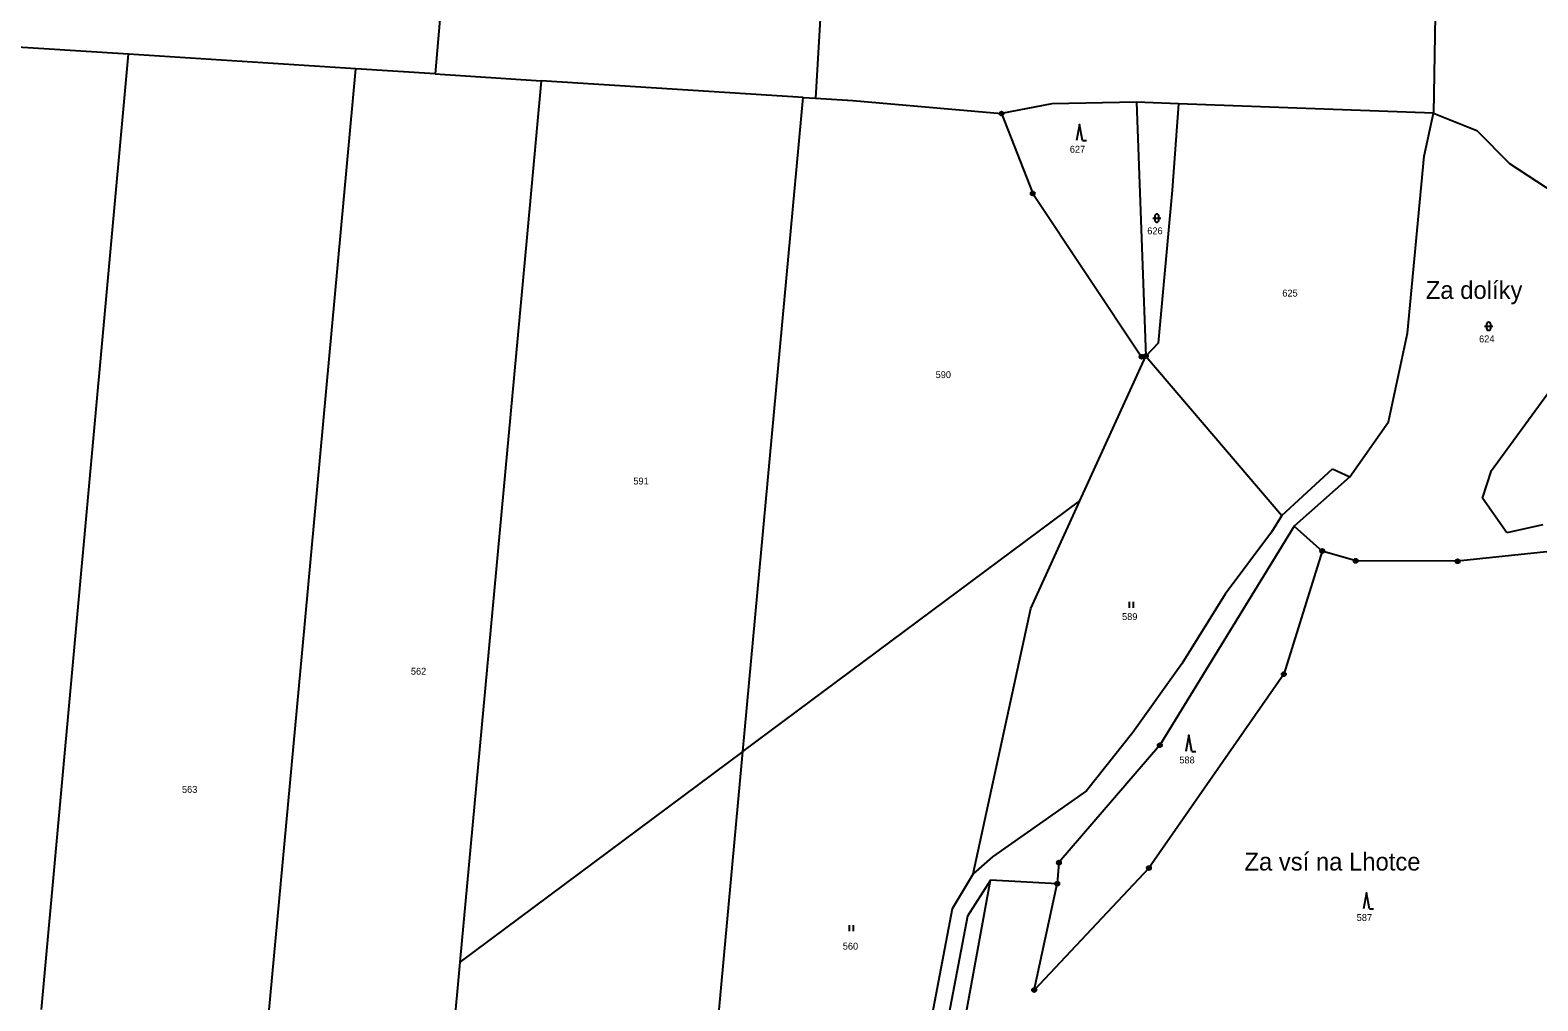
# Model space of a CAD drawing. Extents: x -719614 to -717765, y -1095834 to -1093862.
# Drawn here: x -718922.3 to -718549.9, y -1094941.2 to -1094701.4 of the extents above; entities that cross this region are included whole.
import ezdxf
from ezdxf.enums import TextEntityAlignment as Align

# ---------------------------------------------------------------- set-up
doc = ezdxf.new("R2010")
doc.units = 0
doc.header["$LTSCALE"] = 0.68
for name, color, linetype, lineweight in [('1', 7, 'Continuous', 25), ('3', 7, 'Continuous', 25), ('8', 7, 'Continuous', 25)]:
    doc.layers.add(name, color=color, linetype=linetype, lineweight=lineweight)
doc.layers.add('2', color=7, linetype='Continuous')
doc.layers.add('7', color=7, linetype='Continuous')

msp = doc.modelspace()

# ---------------------------------------------------------------- linework, layer by layer
at = {"layer": '1'}
for p, q in [((-718720.2, -1094577.83), (-718728.32, -1094718.2)), ((-718812.91, -1094600.18), (-718822.27, -1094712.18)), ((-718573.91, -1094620.01), (-718575.68, -1094721.84)), ((-718898.04, -1094707.33), (-718933.96, -1094705.03)), ((-718903.31, -1094765.18), (-718898.04, -1094707.33)), ((-718841.87, -1094710.93), (-718898.04, -1094707.33)), ((-718855.1, -1094854.42), (-718841.87, -1094710.93)), ((-718822.27, -1094712.18), (-718841.87, -1094710.93)), ((-718822.27, -1094712.18), (-718796.11, -1094713.86)), ((-718796.11, -1094713.86), (-718799.68, -1094752.57)), ((-718731.35, -1094718.02), (-718796.11, -1094713.86)), ((-718746.26, -1094879.58), (-718731.35, -1094718.02)), ((-718731.35, -1094718.02), (-718728.32, -1094718.2)), ((-718728.32, -1094718.2), (-718719.14, -1094718.77)), ((-718719.14, -1094718.77), (-718682.38, -1094721.97)), ((-718669.96, -1094719.54), (-718682.38, -1094721.97)), ((-718649.02, -1094719.18), (-718669.96, -1094719.54)), ((-718649.02, -1094719.18), (-718646.71, -1094781.87)), ((-718638.64, -1094719.57), (-718649.02, -1094719.18)), ((-718638.64, -1094719.57), (-718640.2, -1094740.91)), ((-718575.68, -1094721.84), (-718638.64, -1094719.57)), ((-718682.38, -1094721.97), (-718674.67, -1094741.71)), ((-718578, -1094732.52), (-718575.68, -1094721.84)), ((-718575.68, -1094721.84), (-718564.97, -1094726.17)), ((-718564.97, -1094726.17), (-718556.9, -1094734.3)), ((-718582.06, -1094776.22), (-718578, -1094732.52)), ((-718556.9, -1094734.3), (-718532.04, -1094750.61)), ((-718674.67, -1094741.71), (-718647.75, -1094782.05)), ((-718640.2, -1094740.91), (-718643.66, -1094778.71)), ((-718799.68, -1094752.57), (-718816.19, -1094931.59)), ((-718919.54, -1094943.34), (-718903.31, -1094765.18)), ((-718586.75, -1094798.17), (-718582.06, -1094776.22)), ((-718643.66, -1094778.71), (-718646.71, -1094781.87)), ((-718663.01, -1094817.66), (-718646.71, -1094781.87)), ((-718647.75, -1094782.05), (-718646.71, -1094781.87)), ((-718646.71, -1094781.87), (-718613.1, -1094821.27)), ((-718561.31, -1094810.12), (-718545.93, -1094789.06)), ((-718596.31, -1094811.72), (-718586.75, -1094798.17)), ((-718613.1, -1094821.27), (-718600.63, -1094809.75)), ((-718600.63, -1094809.75), (-718596.31, -1094811.72)), ((-718563.56, -1094817.01), (-718561.31, -1094810.12)), ((-718596.31, -1094811.72), (-718610.05, -1094823.95)), ((-718746.26, -1094879.58), (-718663.01, -1094817.66)), ((-718675.12, -1094844.25), (-718663.01, -1094817.66)), ((-718557.52, -1094825.53), (-718563.56, -1094817.01)), ((-718613.1, -1094821.27), (-718615.64, -1094825.4)), ((-718610.05, -1094823.95), (-718643.26, -1094878.03)), ((-718610.05, -1094823.95), (-718603.14, -1094830.05)), ((-718548.67, -1094823.59), (-718557.52, -1094825.53)), ((-718615.64, -1094825.4), (-718627.14, -1094840.69)), ((-718532.55, -1094828.68), (-718569.7, -1094832.59)), ((-718603.14, -1094830.05), (-718612.63, -1094860.48)), ((-718594.87, -1094832.48), (-718603.14, -1094830.05)), ((-718569.7, -1094832.59), (-718594.87, -1094832.48)), ((-718627.14, -1094840.69), (-718637.79, -1094857.89)), ((-718689.41, -1094909.78), (-718675.12, -1094844.25)), ((-718872.09, -1095038.69), (-718855.1, -1094854.42)), ((-718637.79, -1094857.89), (-718649.96, -1094874.92)), ((-718612.63, -1094860.48), (-718645.96, -1094908.38)), ((-718649.96, -1094874.92), (-718661.37, -1094889.28)), ((-718746.26, -1094879.58), (-718816.19, -1094931.59)), ((-718756.62, -1094991.9), (-718746.26, -1094879.58)), ((-718643.26, -1094878.03), (-718668.19, -1094907.03)), ((-718661.37, -1094889.28), (-718684.56, -1094905.62)), ((-718684.56, -1094905.62), (-718689.41, -1094909.78)), ((-718668.19, -1094907.03), (-718668.6, -1094912.24)), ((-718689.41, -1094909.78), (-718694.53, -1094918.47)), ((-718645.96, -1094908.38), (-718674.31, -1094938.52)), ((-718700.77, -1094997.47), (-718685.11, -1094911.36)), ((-718685.11, -1094911.36), (-718690.8, -1094920.26)), ((-718668.6, -1094912.24), (-718685.11, -1094911.36)), ((-718674.31, -1094938.52), (-718668.6, -1094912.24)), ((-718694.53, -1094918.47), (-718701.45, -1094954.74)), ((-718690.8, -1094920.26), (-718697.5, -1094955.37)), ((-718816.19, -1094931.59), (-718822.46, -1094999.63))]:
    msp.add_line(p, q, dxfattribs=at)
at = {"layer": '3'}
for p, q in [((-718662.35, -1094728.66), (-718661.354, -1094728.66)), ((-718645.011, -1094747.821), (-718643.009, -1094747.821)), ((-718644.511, -1094747.321), (-718644.511, -1094748.322)), ((-718643.509, -1094748.322), (-718643.509, -1094747.321)), ((-718563.031, -1094774.521), (-718561.029, -1094774.521)), ((-718562.531, -1094774.021), (-718562.531, -1094775.022)), ((-718561.529, -1094775.022), (-718561.529, -1094774.021)), ((-718650.751, -1094844.12), (-718650.751, -1094842.62)), ((-718649.75, -1094844.12), (-718649.75, -1094842.62)), ((-718635.35, -1094879.54), (-718634.354, -1094879.54)), ((-718591.48, -1094918.47), (-718590.484, -1094918.47)), ((-718719.951, -1094924), (-718719.951, -1094922.5)), ((-718718.95, -1094924), (-718718.95, -1094922.5))]:
    msp.add_line(p, q, dxfattribs=at)
for points in [[(-718662.35, -1094728.66), (-718663.1, -1094724.66), (-718663.85, -1094728.66)], [(-718635.35, -1094879.54), (-718636.1, -1094875.54), (-718636.85, -1094879.54)], [(-718591.48, -1094918.47), (-718592.23, -1094914.47), (-718592.98, -1094918.47)]]:
    msp.add_lwpolyline(points, dxfattribs=at)
for centre, start, end in [((-718644.01, -1094747.3209), 0, 180), ((-718644.01, -1094748.3209), 180, 359.98789), ((-718562.03, -1094774.0209), 0, 180), ((-718562.03, -1094775.0209), 180, 359.98789)]:
    msp.add_arc(centre, 0.5, start, end, dxfattribs=at)
at = {"layer": '8'}
for centre, radius in [((-718682.38, -1094721.9699), 0.5), ((-718682.38, -1094721.9699), 0.0303), ((-718674.67, -1094741.7099), 0.5), ((-718674.67, -1094741.7099), 0.0303), ((-718647.75, -1094782.0499), 0.5), ((-718647.75, -1094782.0499), 0.0303), ((-718646.71, -1094781.8699), 0.5), ((-718646.71, -1094781.8699), 0.0303), ((-718603.14, -1094830.0499), 0.5), ((-718603.14, -1094830.0499), 0.0303), ((-718594.87, -1094832.4799), 0.5), ((-718594.87, -1094832.4799), 0.0303), ((-718569.7, -1094832.5899), 0.5), ((-718569.7, -1094832.5899), 0.0303), ((-718612.63, -1094860.4799), 0.5), ((-718612.63, -1094860.4799), 0.0303), ((-718643.26, -1094878.0299), 0.5), ((-718643.26, -1094878.0299), 0.0303), ((-718668.19, -1094907.0299), 0.5), ((-718668.19, -1094907.0299), 0.0303), ((-718645.96, -1094908.3799), 0.5), ((-718645.96, -1094908.3799), 0.0303), ((-718668.6, -1094912.2399), 0.5), ((-718668.6, -1094912.2399), 0.0303), ((-718674.31, -1094938.5199), 0.5), ((-718674.31, -1094938.5199), 0.0303)]:
    msp.add_circle(centre, radius, dxfattribs=at)

# ---------------------------------------------------------------- texts
at = {"layer": '2'}
for s, p in [('627', (-718663.599, -1094731.642)), ('626', (-718644.469, -1094751.802)), ('625', (-718611.109, -1094767.182)), ('624', (-718562.489, -1094778.502)), ('590', (-718696.749, -1094787.332)), ('591', (-718771.419, -1094813.612)), ('589', (-718650.699, -1094847.102)), ('562', (-718826.389, -1094860.602)), ('588', (-718636.539, -1094882.522)), ('563', (-718882.939, -1094889.802)), ('587', (-718592.729, -1094921.452)), ('560', (-718719.689, -1094928.522))]:
    msp.add_text(s, height=1.7, dxfattribs=at).set_placement(p, align=Align.CENTER)
at = {"layer": '7'}
for s, p in [('Za dolíky', (-718577.56, -1094767.77)), ('Za vsí na Lhotce', (-718622.36, -1094908.98))]:
    msp.add_text(s, height=4.4, dxfattribs=at).set_placement(p)

doc.saveas('drawing.dxf')
